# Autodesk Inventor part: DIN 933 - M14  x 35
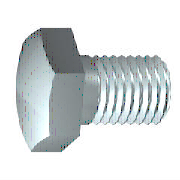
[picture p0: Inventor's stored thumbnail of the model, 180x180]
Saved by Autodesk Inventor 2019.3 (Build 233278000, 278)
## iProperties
Created: 2018-01
Part Number: DIN 933 - M14  x 35
Material: Ocel, měkká
Description: Šestihranný šroub
Document SubType Name: Modeling
Standard: DIN 933
Designer: B-hon
Standards Organization: DIN
Language: cs-CZ
Size Designation: M14  x 35
Categories: <MemberInstance><Categories><Category DisplayName="Spojovací materiál" InternalName="e4da775c-781d-43d5-af7c-5136215cf5a6" Mnemonic="FSTN"><Category DisplayName
Density: 7.85 g/cm^3
Appearance: Pololeštěná
IsCustomPart: 0
Author: B-hon
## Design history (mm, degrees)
sketch "Náčrt1"
  geometry: L1 (0, 10.05)-(0, 6.459); L2 (6, 7)-(35, 7); L3 (35, 7)-(35, 0); L4 (35, 0)-(-0.6, 0); L5 (-7.72, 0)-(42.12, 0) reference; L6 (-0.6, 0)-(-0.6, 10.05); L7 (-0.6, 10.05)-(0, 10.05); L8 (6, 7)-(4.773, 6.459); L9 (4.773, 6.459)-(0, 6.459); L10 (0, -2.01)-(0, 12.06) reference
  constraints: 16 end point, 2 collinear, 2 perpendicular, 1 parallel
  dimensions: "d0" = 35 distance between parallel lines of L3 L1 (= NLG); "d1" = 29 distance from line of L2.start L3 (= GEL); "d2" = 14 diameter of L2 L4 (= GD); "d9" = 0.6001 distance between parallel lines of L6 L1 (computed from SD); "d10" = 20.1 diameter of L7 L4 (= SD2); "d13" = 1.227 horizontal distance of L2.start L8.end (computed from GAL); "d14" = 12.91747 diameter of L9 L4 (= BDM)
revolve "Těleso" sketch "Náčrt1" stored, may be unused: angle "d12" = 90 deg
sketch "Náčrt2"
  geometry: L1 (0, 12.702)-(11, 6.351); L2 (11, 6.351)-(11, -6.351); L3 (11, -6.351)-(0, -12.702); L4 (0, -12.702)-(-11, -6.351); L5 (-11, -6.351)-(-11, 6.351); L6 (-11, 6.351)-(0, 12.702); 2 further points
  constraints: 12 end point, 1 coincident, 1 vertical, 11 other
  dimensions: "d11" = 22 distance between parallel lines of L5 L2 (= SW)
extrude "Hlava" join sketch "Náčrt2" distance "d3" = 8.2 (= KOH - SD); taper "d4" = 0 deg
sketch "Náčrt4"
  geometry: L1 (-8.8, 11)-(-8.8, 12.702); L2 (-8.8, 12.702)-(-7.818, 12.702); L3 (-7.818, 12.702)-(-8.8, 11); L4 (-10.44, 0)-(1.04, 0) reference; L5 (-0.6, 12.702)-(-8.8, 12.702) reference; L6 (-8.8, 6.351)-(-8.8, 12.702) reference
  constraints: 6 end point, 2 collinear, 1 perpendicular, 1 vertical
  dimensions: "d5" = 30 deg angle of L3 L1 (= ANG1); "d19" = 22 diameter of L1.start L4 (= SW0)
revolve "Zkosení1" sketch "Náčrt4" stored, may be unused: angle "d21" = 90 deg
workplane "Work Plane1"
body "Solid1"
feature "Závit" dims "d15" = 29 (= GEL), "d16" = 0
chamfer "Zkosení2" distance "d6" = 1.2269 (= -0.5 x SPD + 0.5 x GD); stored, may be unused: second distance "d7" = 1.227 (computed from GUL), angle "d55" = 45 deg
other parameters: "NLG" = 35 [user parameter; used in 1 equation term], "GD" = 14 (= NND) [user parameter; used in 2 equation terms], "BDM" = 12.91747 [user parameter; used in 1 equation term], "KOH" = 8.8 [user parameter; used in 1 equation term], "GEL" = 29 [user parameter; used in 2 equation terms], "SW" = 22 [user parameter; used in 2 equation terms], "SW0" = 22 [user parameter; used in 1 equation term], "SPD" = 11.5462 (= NND - 1.2269 x PTC) [user parameter; used in 1 equation term], "SD2" = 20.1 [user parameter; used in 1 equation term], "SD" = 0.6 [user parameter; used in 2 equation terms], "ANG1" = 30 deg [user parameter; used in 1 equation term], "GAL" = 1.2269 (= 0.61345 x PTC) [user parameter; used in 1 equation term], "GUL" = 1.2269 (= 0.61345 x PTC) [user parameter; used in 1 equation term], "d8" = 0, "RR" = 0.6 [user parameter], "d57" = 0, "d58" = 0, "TPU" = 5 (computed from PTC) [user parameter], "GD1" = 11.5462 (= THREADDIA - 1.2269 x PTC) [user parameter], "THREADDIA" = 14 [user parameter; used in 1 equation term], "TOA" = 30 deg [user parameter], "PTC" = 2 [user parameter; used in 5 equation terms], "NND" = 14 [user parameter; used in 2 equation terms], "E0" = 25.41 (= 1.155 x SW) [user parameter]
